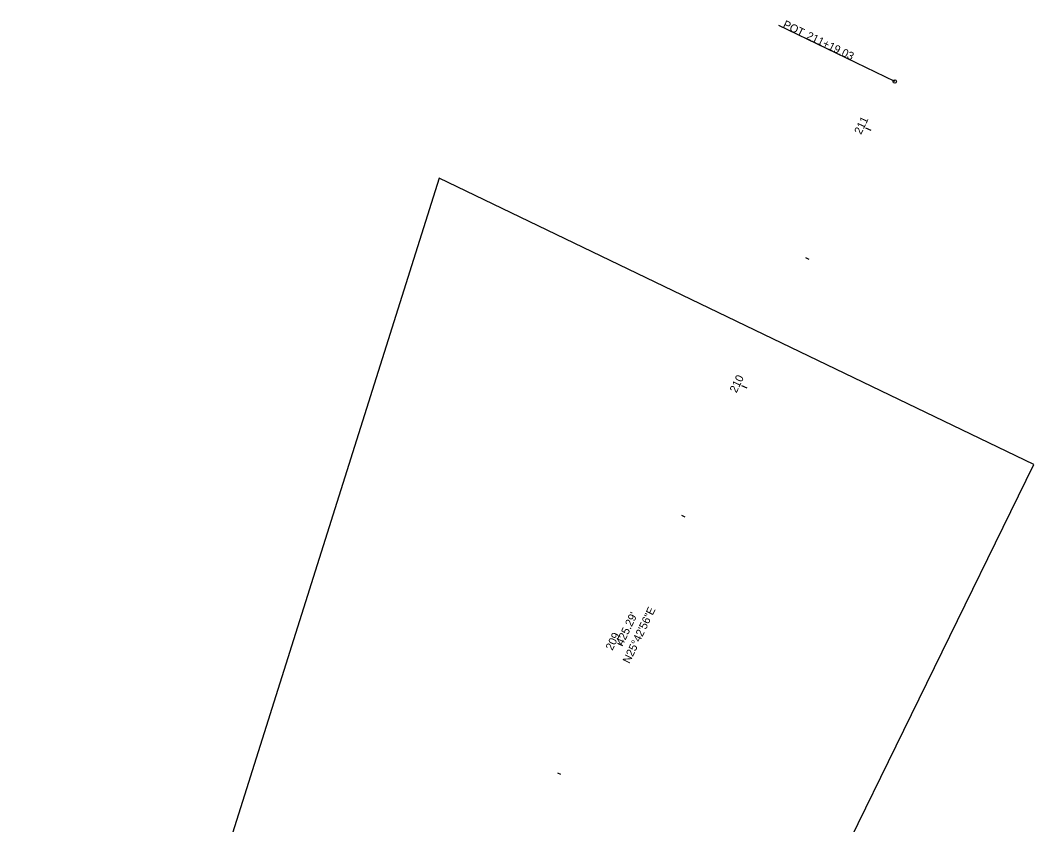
# Model space of a CAD drawing. Extents: x 1564517 to 1565226, y 635740 to 637455.
# Drawn here: x 1564871.5 to 1565225.9, y 637022.2 to 637303.5 of the extents above; entities that cross this region are included whole.
import ezdxf

# ---------------------------------------------------------------- set-up
doc = ezdxf.new("R2010")
doc.units = 0
for name, color, linetype in [('GE_P_Alignment_1000_Bearings', 7, 'Continuous'), ('GE_P_Alignment_1000_Cardinal_Points', 7, 'Continuous'), ('GE_P_Alignment_1000_Distances', 7, 'Continuous'), ('GE_P_Alignment_1000_Stations', 7, 'Continuous'), ('GE_P_Alignment_100_Bearings', 7, 'Continuous'), ('GE_P_Alignment_100_Cardinal_Points', 7, 'Continuous'), ('GE_P_Alignment_100_Distances', 7, 'Continuous'), ('GE_P_Alignment_100_Stations', 7, 'Continuous'), ('GE_P_Alignment_500_Bearings', 7, 'Continuous'), ('GE_P_Alignment_500_Cardinal_Points', 7, 'Continuous'), ('GE_P_Alignment_500_Distances', 7, 'Continuous'), ('GE_P_Alignment_500_Stations', 7, 'Continuous'), ('SH_Named_Boundary', 7, 'Continuous')]:
    doc.layers.add(name, color=color, linetype=linetype)

msp = doc.modelspace()

# ---------------------------------------------------------------- linework, layer by layer
at = {"layer": 'GE_P_Alignment_1000_Cardinal_Points'}
msp.add_line((1565177.32, 637282.11), (1565136.78, 637301.64), dxfattribs=at)
msp.add_circle((1565177.32, 637282.11), 0.6, dxfattribs=at)
at = {"layer": 'GE_P_Alignment_1000_Stations'}
msp.add_line((1565125.67, 637174.87), (1565123.87, 637175.74), dxfattribs=at)
at = {"layer": 'GE_P_Alignment_100_Cardinal_Points'}
msp.add_line((1565177.32, 637282.11), (1565136.78, 637301.64), dxfattribs=at)
msp.add_circle((1565177.32, 637282.11), 0.6, dxfattribs=at)
at = {"layer": 'GE_P_Alignment_100_Stations'}
for p, q in [((1565169.06, 637264.97), (1565167.26, 637265.83)), ((1565147.37, 637219.92), (1565146.29, 637220.44)), ((1565125.67, 637174.87), (1565123.87, 637175.74)), ((1565103.98, 637129.82), (1565102.9, 637130.34)), ((1565082.28, 637084.78), (1565080.48, 637085.64)), ((1565060.59, 637039.73), (1565059.51, 637040.25))]:
    msp.add_line(p, q, dxfattribs=at)
at = {"layer": 'GE_P_Alignment_500_Cardinal_Points'}
msp.add_line((1565177.32, 637282.11), (1565136.78, 637301.64), dxfattribs=at)
msp.add_circle((1565177.32, 637282.11), 0.6, dxfattribs=at)
at = {"layer": 'GE_P_Alignment_500_Stations'}
for p, q in [((1565169.06, 637264.97), (1565167.98, 637265.49)), ((1565125.67, 637174.87), (1565123.87, 637175.74)), ((1565082.28, 637084.78), (1565081.2, 637085.3))]:
    msp.add_line(p, q, dxfattribs=at)
at = {"layer": 'SH_Named_Boundary'}
msp.add_lwpolyline([(1564858.24, 636742.53), (1565001.39, 636689.39), (1565225.94, 637148.15), (1565017.94, 637248.32)], close=True, dxfattribs=at)

# ---------------------------------------------------------------- texts
at = {"layer": 'GE_P_Alignment_1000_Bearings'}
msp.add_text('N25°42\'56"E', height=2.8, rotation=64.2844, dxfattribs=at).set_placement((1565084.53, 637078.37))
at = {"layer": 'GE_P_Alignment_1000_Cardinal_Points'}
for s, p in [('POT', (1565137.95, 637301.12)), ('211+19.03', (1565146.18, 637297.16))]:
    msp.add_text(s, height=2.8, rotation=334.2844, dxfattribs=at).set_placement(p)
at = {"layer": 'GE_P_Alignment_1000_Distances'}
msp.add_text("425.29'", height=2.8, rotation=64.2844, dxfattribs=at).set_placement((1565082.2, 637084.71))
at = {"layer": 'GE_P_Alignment_1000_Stations'}
msp.add_text('210', height=2.8, rotation=64.2844, dxfattribs=at).set_placement((1565121.95, 637173.02))
at = {"layer": 'GE_P_Alignment_100_Bearings'}
msp.add_text('N25°42\'56"E', height=2.8, rotation=64.2844, dxfattribs=at).set_placement((1565084.53, 637078.37))
at = {"layer": 'GE_P_Alignment_100_Cardinal_Points'}
for s, p in [('POT', (1565137.95, 637301.12)), ('211+19.03', (1565146.18, 637297.16))]:
    msp.add_text(s, height=2.8, rotation=334.2844, dxfattribs=at).set_placement(p)
at = {"layer": 'GE_P_Alignment_100_Distances'}
msp.add_text("425.29'", height=2.8, rotation=64.2844, dxfattribs=at).set_placement((1565082.2, 637084.71))
at = {"layer": 'GE_P_Alignment_100_Stations'}
for s, p in [('211', (1565165.52, 637263.38)), ('210', (1565121.95, 637173.02)), ('209', (1565078.58, 637082.95))]:
    msp.add_text(s, height=2.8, rotation=64.2844, dxfattribs=at).set_placement(p)
at = {"layer": 'GE_P_Alignment_500_Bearings'}
msp.add_text('N25°42\'56"E', height=2.8, rotation=64.2844, dxfattribs=at).set_placement((1565084.53, 637078.37))
at = {"layer": 'GE_P_Alignment_500_Cardinal_Points'}
for s, p in [('POT', (1565137.95, 637301.12)), ('211+19.03', (1565146.18, 637297.16))]:
    msp.add_text(s, height=2.8, rotation=334.2844, dxfattribs=at).set_placement(p)
at = {"layer": 'GE_P_Alignment_500_Distances'}
msp.add_text("425.29'", height=2.8, rotation=64.2844, dxfattribs=at).set_placement((1565082.2, 637084.71))
at = {"layer": 'GE_P_Alignment_500_Stations'}
msp.add_text('210', height=2.8, rotation=64.2844, dxfattribs=at).set_placement((1565121.95, 637173.02))

doc.saveas('drawing.dxf')
